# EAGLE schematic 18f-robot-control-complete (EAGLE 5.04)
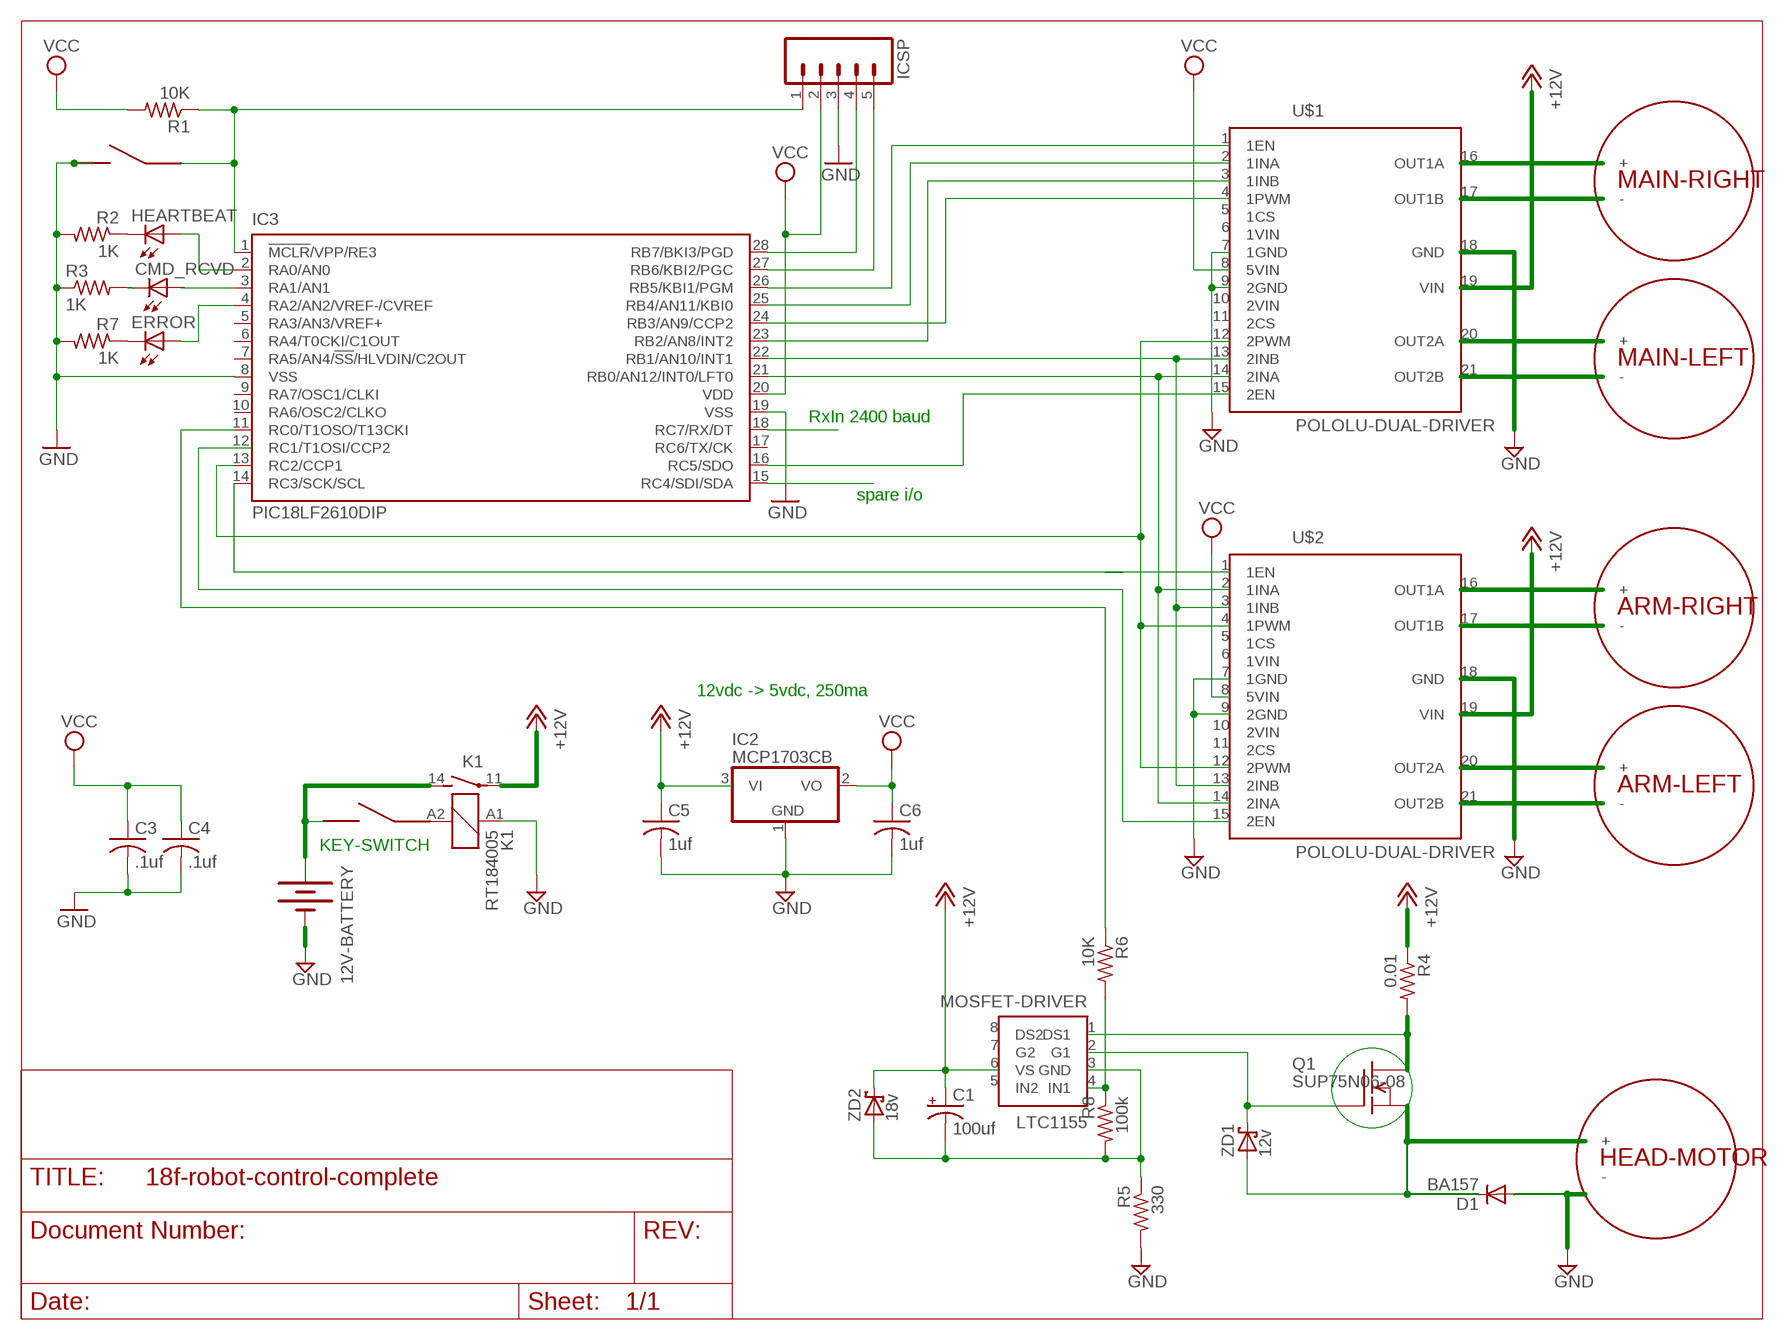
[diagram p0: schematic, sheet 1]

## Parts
12V-BATTERY  BATTERYAA  [BATTERY-AA]
ARM-LEFT  DC-MOTOR  [DC-MOTOR]
ARM-RIGHT  DC-MOTOR  [DC-MOTOR]
C1  100uf  CPOL-US140CLH-1010  [140CLH-1010]
C3  .1uf  C-US102-043X133  [C102-043X133]
C4  .1uf  C-US102-043X133  [C102-043X133]
C5  1uf  C-US102-043X133  [C102-043X133]
C6  1uf  C-US102-043X133  [C102-043X133]
CMD_RCVD  LEDCHIPLED_0603  [CHIPLED_0603]
D1  BA157  [P1-10]
ERROR  LEDCHIPLED_0603  [CHIPLED_0603]
HEAD-MOTOR  DC-MOTOR  [DC-MOTOR]
HEARTBEAT  LEDCHIPLED_0603  [CHIPLED_0603]
IC2  MCP1703CB  [SOT23]
IC3  PIC18LF2610DIP  [DIL28-3]
ICSP  M05  [05P]
K1  RT184005  [RT-N/O12A3.5]
KEY-SWITCH  KEY-SWITCH  PUSH-BUTTON-SWITCH  [2SIL]
MAIN-LEFT  DC-MOTOR  [DC-MOTOR]
MAIN-RIGHT  DC-MOTOR  [DC-MOTOR]
MOSFET-DRIVER  LTC1155  [8DIP]
Q1  SUP75N06-08  [TO220]
R1  10K  R-US_0617/22  [0617/22]
R2  1K  R-US_0617/22  [0617/22]
R3  1K  R-US_0617/22  [0617/22]
R4  0.01  R-US_0617/22  [0617/22]
R5  330  R-US_0617/22  [0617/22]
R6  10K  R-US_0617/22  [0617/22]
R7  1K  R-US_0617/22  [0617/22]
R8  100k  R-US_0617/22  [0617/22]
RESET  PUSH-BUTTON-SWITCH  [2SIL]
U$1  POLOLU-DUAL-DRIVER  [POLOLU-DUAL-DRIVER]
U$2  POLOLU-DUAL-DRIVER  [POLOLU-DUAL-DRIVER]
ZD1  12v  1N6267A  [C4111-15]
ZD2  18v  1N6267A  [C4111-15]

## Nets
+12V: C1.+ C5.1 IC2.3(VI) K1.11(2:P) MOSFET-DRIVER.6(VS) R4.1 U$1.19(VIN) U$2.19(VIN) ZD2.C
GND: 12V-BATTERY.GND@1(-) C3.2 C4.2 C5.2 C6.2 D1.A IC2.1(GND) IC3.8(VSS) IC3.19(VSS) ICSP.3 K1.A1 R2.2 R3.1 R5.2 R7.2 RESET.COM U$1.7(1GND) U$1.9(2GND) U$1.18(GND) U$2.7(1GND) U$2.9(2GND) U$2.18(GND)
N$1: HEARTBEAT.C R2.1
N$2: CMD_RCVD.C R3.2
N$3: MAIN-RIGHT.P$2(-) U$1.17(OUT1B)
N$4: MAIN-RIGHT.P$1(+) U$1.16(OUT1A)
N$5: HEARTBEAT.A IC3.2(RA0/AN0)
N$6: IC3.27(RB6/KBI2/PGC) ICSP.5
N$8: MAIN-LEFT.P$1(+) U$1.20(OUT2A)
N$9: IC3.18(RC7/RX/DT)
N$10: IC3.28(RB7/BKI3/PGD) ICSP.4
N$11: ERROR.C R7.1
N$12: IC3.24(RB3/AN9/CCP2) U$1.4(1PWM)
N$13: IC3.13(RC2/CCP1) U$1.12(2PWM) U$2.4(1PWM) U$2.12(2PWM)
N$14: MAIN-LEFT.P$2(-) U$1.21(OUT2B)
N$15: IC3.14(RC3/SCK/SCL) U$2.1(1EN)
N$16: ERROR.A IC3.4(RA2/AN2/VREF-/CVREF)
N$17: CMD_RCVD.A IC3.3(RA1/AN1)
N$18: IC3.21(RB0/AN12/INT0/LFT0) U$1.14(2INA) U$2.2(1INA) U$2.14(2INA)
N$19: IC3.15(RC4/SDI/SDA)
N$21: IC3.25(RB4/AN11/KBI0) U$1.2(1INA)
N$22: IC3.23(RB2/AN8/INT2) U$1.3(1INB)
N$23: MOSFET-DRIVER.2(G1) Q1.1(G) ZD1.C
N$24: IC3.16(RC5/SDO) U$1.15(2EN)
N$25: MOSFET-DRIVER.3(GND) R5.1
N$26: MOSFET-DRIVER.1(DS1) Q1.2(D) R4.2
N$28: ICSP.1 R1.1 RESET.NO
N$29: K1.A2 KEY-SWITCH.NO
N$30: 12V-BATTERY.PWR@1(+) K1.14(2:S) KEY-SWITCH.COM
N$31: IC3.26(RB5/KBI1/PGM) U$1.1(1EN)
N$32: MOSFET-DRIVER.4(IN1) R6.2 R8.1
N$33: IC3.11(RC0/T1OSO/T13CKI) R6.1
N$34: C1.- R8.2 ZD2.A
N$37: D1.C HEAD-MOTOR.P$1(+) Q1.3(S) ZD1.A
N$38: ARM-LEFT.P$1(+) U$2.20(OUT2A)
N$39: ARM-LEFT.P$2(-) U$2.21(OUT2B)
N$40: ARM-RIGHT.P$2(-) U$2.17(OUT1B)
N$41: ARM-RIGHT.P$1(+) U$2.16(OUT1A)
N$42: U$2.15(2EN)
N$54: IC3.22(RB1/AN10/INT1) U$1.13(2INB) U$2.3(1INB) U$2.13(2INB)
VCC: C3.1 C4.1 C6.1 IC2.2(VO) IC3.20(VDD) ICSP.2 R1.2 U$1.8(5VIN) U$2.8(5VIN)
Unconnected: HEAD-MOTOR.P$2(-) IC3.1(!MCLR!/VPP/RE3) IC3.5(RA3/AN3/VREF+) IC3.6(RA4/T0CKI/C1OUT) IC3.7(RA5/AN4/!SS!/HLVDIN/C2OUT) IC3.9(RA7/OSC1/CLKI) IC3.10(RA6/OSC2/CLKO) IC3.12(RC1/T1OSI/CCP2) IC3.17(RC6/TX/CK) MOSFET-DRIVER.5(IN2) MOSFET-DRIVER.7(G2) MOSFET-DRIVER.8(DS2) U$1.5(1CS) U$1.6(1VIN) U$1.10(2VIN) U$1.11(2CS) U$2.5(1CS) U$2.6(1VIN) U$2.10(2VIN) U$2.11(2CS)

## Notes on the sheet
- RxIn 2400 baud
- spare i/o
- 12vdc -> 5vdc, 250ma
- KEY-SWITCH

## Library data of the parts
12V-BATTERY = SparkFun:BATTERY: Battery Holders
ARM-LEFT ARM-RIGHT HEAD-MOTOR MAIN-LEFT MAIN-RIGHT = trl:DC-MOTOR: DC Motor
C1 = rcl:CPOL-US: POLARIZED CAPACITOR, American symbol
C3-C6 = rcl:C-US: CAPACITOR, American symbol
CMD_RCVD ERROR HEARTBEAT = led:LED: LED
D1 = diode:BA157: DIODE
IC2 = linear:MCP1703: 250 mA, 16V, Low Quiescent Current LDO Regulator Source: http://ww1.microchip.com/downloads/en/DeviceDoc/22049b.pdf
IC3 = trl:PIC18LF2610: PIC18LF2610 28-Pin, No USB or EEPROM
ICSP = con-amp-quick:M05: AMP QUICK CONNECTOR
K1 = relay:RT?*: Power PCB Relay SCHRACK 1 pole 12 / 16 A, DC- or AC-coil Source: http://www.schrack.com/.. 5819.pdf
KEY-SWITCH RESET = trl:PUSH-BUTTON-SWITCH
MOSFET-DRIVER = trl:LTC1155
Q1 = transistor-fet:SUP75N06-08: N-Channel Enhancement MOSFET 60V; 75A; 0,008Ohm
R1-R8 = resistor:R-US_: RESISTOR, American symbol
U$1 U$2 = trl:POLOLU-DUAL-DRIVER
ZD1 ZD2 = diode:1N6267A: DIODE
